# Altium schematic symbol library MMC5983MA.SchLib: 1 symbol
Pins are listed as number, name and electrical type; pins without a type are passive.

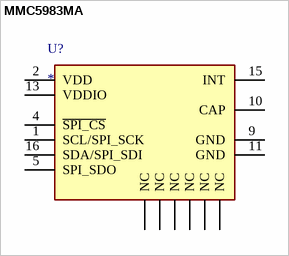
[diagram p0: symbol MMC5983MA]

## MMC5983MA
designator U?
MMC5983 series Magnetic, Magnetometer Sensor Evaluation Board; MF: Memsic Inc.; MP: MMC5983MA
footprint PQFN50P300X300X100-16N
pins: 1 SCL/SPI_SCK, 2 VDD, 3 NC, 4 ~{SPI_CS}, 5 SPI_SDO, 6 NC, 7 NC, 8 NC, 9 GND, 10 CAP, 11 GND, 12 NC, 13 VDDIO, 14 NC, 15 INT, 16 SDA/SPI_SDI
